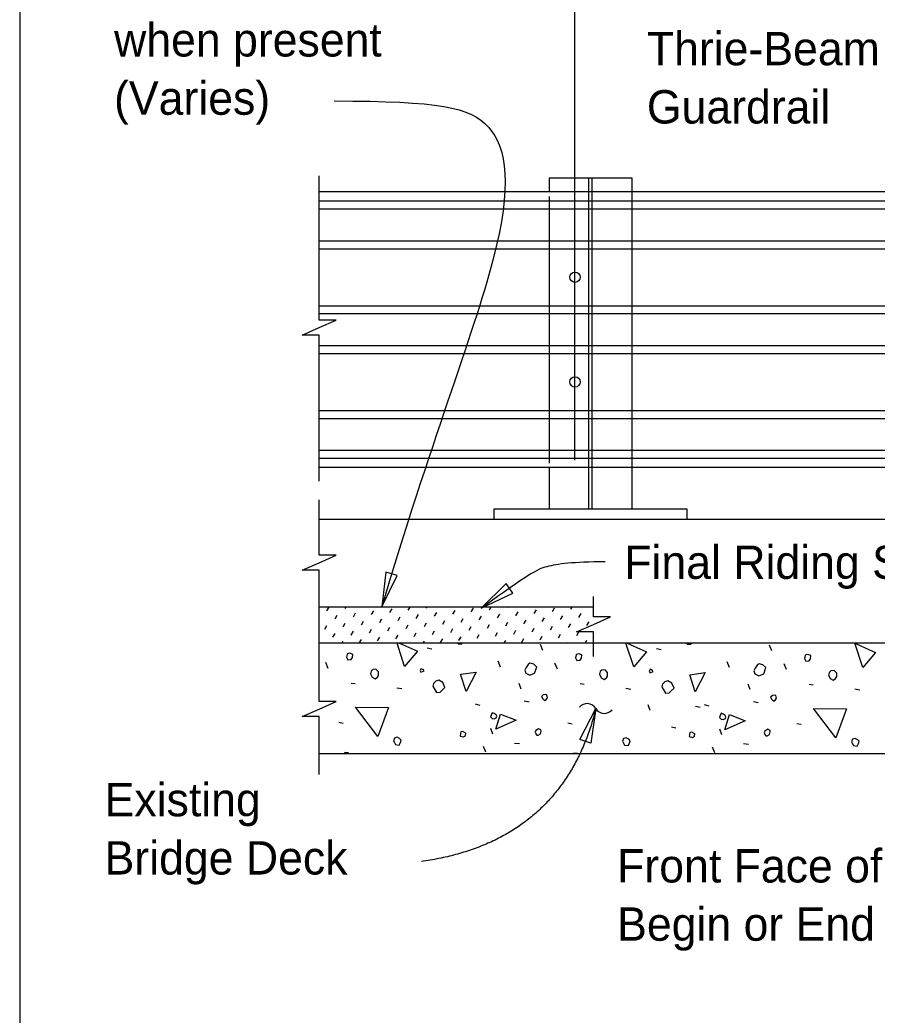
# Model space of a CAD drawing. Extents: x 21587 to 21656.3, y 56117.4 to 56157.3.
# Drawn here: x 21605.5 to 21610.68, y 56131.8 to 56137.82 of the extents above; entities that cross this region are included whole.
import ezdxf

# ---------------------------------------------------------------- set-up
doc = ezdxf.new("R2010")
doc.units = 0
for name, color, linetype in [('AdhocPoint_dp', 7, 'Continuous'), ('Border', 7, 'Continuous'), ('Patterning', 7, 'Continuous'), ('PlotBorder_dp', 7, 'Continuous'), ('SheetBorder_dp', 7, 'Continuous'), ('TextMisc', 7, 'Continuous')]:
    doc.layers.add(name, color=color, linetype=linetype)

msp = doc.modelspace()

# ---------------------------------------------------------------- linework, layer by layer
at = {"layer": 'AdhocPoint_dp'}
for p, q in [((21607.3117, 56134.8009), (21613.4854, 56134.8009)), ((21608.9696, 56134.2699), (21607.3116, 56134.2699)), ((21613.4854, 56134.0509), (21607.3117, 56134.0509)), ((21607.3117, 56133.3843), (21613.4854, 56133.3843))]:
    msp.add_line(p, q, dxfattribs=at)
at = {"layer": 'Border'}
for p, q in [((21608.7018, 56136.8635), (21609.2018, 56136.8635)), ((21608.7018, 56136.8635), (21608.7018, 56136.7802)), ((21609.2018, 56136.8635), (21609.2018, 56136.7802)), ((21619.5663, 56136.7801), (21607.3117, 56136.7801)), ((21607.3117, 56136.7246), (21619.5663, 56136.7246)), ((21607.3117, 56136.6764), (21619.5663, 56136.6764)), ((21607.3117, 56136.4835), (21619.5663, 56136.4835)), ((21607.3117, 56136.4353), (21619.5663, 56136.4353)), ((21607.3117, 56136.0914), (21619.5663, 56136.0914)), ((21607.3117, 56136.0431), (21619.5663, 56136.0431)), ((21607.3117, 56135.8503), (21619.5663, 56135.8503)), ((21607.3117, 56135.8022), (21619.5663, 56135.8022)), ((21607.3117, 56135.4582), (21619.5663, 56135.4582)), ((21607.3117, 56135.41), (21619.5663, 56135.41)), ((21607.3117, 56135.2172), (21619.5663, 56135.2172)), ((21607.3117, 56135.169), (21619.5663, 56135.169)), ((21619.5663, 56135.1134), (21607.3117, 56135.1134)), ((21608.7018, 56135.1135), (21608.7018, 56134.8635)), ((21609.2018, 56135.1134), (21609.2018, 56134.8635)), ((21608.3685, 56134.8635), (21609.5351, 56134.8635)), ((21608.3685, 56134.801), (21608.3685, 56134.8635)), ((21608.7018, 56134.8635), (21609.2018, 56134.8635)), ((21609.5351, 56134.8635), (21609.5351, 56134.801)), ((21608.3685, 56134.801), (21609.5351, 56134.801))]:
    msp.add_line(p, q, dxfattribs=at)
for centre in [(21608.858, 56136.2634), (21608.858, 56135.6303)]:
    msp.add_circle(centre, 0.0312, dxfattribs=at)
at = {"layer": 'Patterning'}
for p, q in [((21608.9414, 56134.8635), (21608.9414, 56136.8635)), ((21608.9622, 56134.8635), (21608.9622, 56136.8635)), ((21608.7018, 56136.7516), (21608.7018, 56135.1398)), ((21609.2018, 56136.7801), (21609.2018, 56135.1134))]:
    msp.add_line(p, q, dxfattribs=at)
at = {"layer": 'PlotBorder_dp'}
for p, q in [((21605.5022, 56153.2556), (21605.5022, 56127.3172)), ((21608.858, 56135.1577), (21608.858, 56143.2258))]:
    msp.add_line(p, q, dxfattribs=at)
for points in [[(21607.3117, 56135.0303), (21607.3117, 56135.9135), (21607.2084, 56135.9135), (21607.3117, 56135.9585), (21607.4151, 56136.0035), (21607.3117, 56136.0035), (21607.3117, 56136.8765)], [(21607.3117, 56134.0229), (21607.3117, 56134.493), (21607.2084, 56134.493), (21607.3117, 56134.538), (21607.4151, 56134.583), (21607.3117, 56134.583), (21607.3117, 56134.9175)], [(21608.9697, 56133.972), (21608.9697, 56134.1198), (21608.8664, 56134.1198), (21608.9697, 56134.1648), (21609.073, 56134.2098), (21608.9697, 56134.2098), (21608.9697, 56134.3343)], [(21607.3117, 56133.2578), (21607.3117, 56133.6084), (21607.2084, 56133.6084), (21607.3117, 56133.6534), (21607.4151, 56133.6984), (21607.3117, 56133.6984), (21607.3117, 56134.0229)]]:
    msp.add_lwpolyline(points, dxfattribs=at)
for points in [[(21607.6902, 56134.2707), (21607.7828, 56134.4606), (21607.7151, 56134.4805)], [(21608.2911, 56134.2633), (21608.4817, 56134.3543), (21608.4411, 56134.412)], [(21608.9843, 56133.6565), (21608.9539, 56133.4475), (21608.8867, 56133.4692)]]:
    msp.add_lwpolyline(points, close=True, dxfattribs=at)
for centre, start, end in [((21608.9319, 56133.6269), 30.00813, 141.73535), ((21609.0352, 56133.6865), 210.00813, 321.73535)]:
    msp.add_arc(centre, 0.0596, start, end, dxfattribs=at)
for points, degree in [([(21607.4013, 56137.3293), (21608.0354, 56137.3258), (21608.4135, 56137.2664), (21608.5135, 56136.5948), (21607.9729, 56135.2323), (21607.6902, 56134.2708)], 3), ([(21609.0397, 56134.5436), (21608.8463, 56134.5415), (21608.6579, 56134.5211), (21608.5865, 56134.4713), (21608.2911, 56134.2634)], 3), ([(21608.9843, 56133.6565), (21608.7812, 56132.8522), (21607.9297, 56132.7319)], 2)]:
    msp.add_open_spline(points, degree=degree, dxfattribs=at)
at = {"layer": 'TextMisc'}
for p, q in [((21607.3586, 56134.2474), (21607.3715, 56134.2698)), ((21607.4692, 56134.2604), (21607.4747, 56134.2699)), ((21607.8499, 56134.2504), (21607.8612, 56134.2699)), ((21607.9606, 56134.2634), (21607.9643, 56134.2699)), ((21608.3413, 56134.2535), (21608.3508, 56134.2699)), ((21608.4519, 56134.2664), (21608.4539, 56134.2699)), ((21608.722, 56134.2435), (21608.735, 56134.2659)), ((21608.8327, 56134.2565), (21608.8404, 56134.2699)), ((21608.9433, 56134.2695), (21608.9436, 56134.2699)), ((21607.4074, 56134.1986), (21607.4204, 56134.221)), ((21607.518, 56134.2116), (21607.531, 56134.234)), ((21607.6287, 56134.2245), (21607.6416, 56134.2469)), ((21607.7393, 56134.2375), (21607.7523, 56134.2599)), ((21607.7881, 56134.1887), (21607.8011, 56134.211)), ((21607.8988, 56134.2016), (21607.9117, 56134.224)), ((21608.0094, 56134.2146), (21608.0224, 56134.237)), ((21608.12, 56134.2275), (21608.133, 56134.2499)), ((21608.2307, 56134.2405), (21608.2436, 56134.2629)), ((21608.2795, 56134.1917), (21608.2925, 56134.2141)), ((21608.3901, 56134.2046), (21608.4031, 56134.227)), ((21608.5008, 56134.2176), (21608.5137, 56134.24)), ((21608.6114, 56134.2306), (21608.6244, 56134.253)), ((21608.7709, 56134.1947), (21608.7838, 56134.2171)), ((21608.8815, 56134.2077), (21608.8945, 56134.23)), ((21607.3456, 56134.1368), (21607.3586, 56134.1592)), ((21607.4562, 56134.1498), (21607.4692, 56134.1722)), ((21607.5669, 56134.1627), (21607.5798, 56134.1851)), ((21607.6775, 56134.1757), (21607.6905, 56134.1981)), ((21607.7263, 56134.1269), (21607.7393, 56134.1492)), ((21607.837, 56134.1398), (21607.8499, 56134.1622)), ((21607.9476, 56134.1528), (21607.9606, 56134.1752)), ((21608.0582, 56134.1657), (21608.0712, 56134.1881)), ((21608.1689, 56134.1787), (21608.1818, 56134.2011)), ((21608.2177, 56134.1299), (21608.2307, 56134.1523)), ((21608.3283, 56134.1428), (21608.3413, 56134.1652)), ((21608.439, 56134.1558), (21608.4519, 56134.1782)), ((21608.5496, 56134.1688), (21608.5626, 56134.1912)), ((21608.6602, 56134.1817), (21608.6732, 56134.2041)), ((21608.7091, 56134.1329), (21608.722, 56134.1553)), ((21608.8197, 56134.1459), (21608.8327, 56134.1682)), ((21608.9303, 56134.1588), (21608.9433, 56134.1812)), ((21607.3944, 56134.088), (21607.4074, 56134.1104)), ((21607.5051, 56134.1009), (21607.518, 56134.1233)), ((21607.6157, 56134.1139), (21607.6287, 56134.1363)), ((21607.6645, 56134.0651), (21607.6775, 56134.0874)), ((21607.7752, 56134.078), (21607.7881, 56134.1004)), ((21607.8858, 56134.091), (21607.8988, 56134.1134)), ((21607.9964, 56134.1039), (21608.0094, 56134.1263)), ((21608.1071, 56134.1169), (21608.12, 56134.1393)), ((21608.1559, 56134.0681), (21608.1689, 56134.0905)), ((21608.2665, 56134.081), (21608.2795, 56134.1034)), ((21608.3772, 56134.094), (21608.3901, 56134.1164)), ((21608.4878, 56134.107), (21608.5008, 56134.1294)), ((21608.5984, 56134.1199), (21608.6114, 56134.1423)), ((21608.6473, 56134.0711), (21608.6602, 56134.0935)), ((21608.7579, 56134.0841), (21608.7709, 56134.1065)), ((21608.8685, 56134.097), (21608.8815, 56134.1194)), ((21608.9792, 56134.11), (21608.9793, 56134.1102)), ((21607.4501, 56134.0509), (21607.4562, 56134.0615)), ((21607.5539, 56134.0521), (21607.5669, 56134.0745)), ((21607.8366, 56134.0509), (21607.837, 56134.0516)), ((21607.9397, 56134.0509), (21607.9476, 56134.0645)), ((21608.0453, 56134.0551), (21608.0582, 56134.0775)), ((21608.3262, 56134.0509), (21608.3283, 56134.0546)), ((21608.4293, 56134.0509), (21608.439, 56134.0676)), ((21608.5366, 56134.0581), (21608.5496, 56134.0805)), ((21608.6635, 56134.0079), (21608.6494, 56134.0432)), ((21608.8158, 56134.0509), (21608.8197, 56134.0576)), ((21608.919, 56134.0509), (21608.9303, 56134.0706)), ((21610.0482, 56134.0043), (21610.034, 56134.0397)), ((21607.9652, 56134.0238), (21607.9935, 56134.0167)), ((21609.3499, 56134.0203), (21609.3782, 56134.0132)), ((21607.3666, 56133.8989), (21607.3524, 56133.9343)), ((21608.4072, 56133.9071), (21608.393, 56133.9425)), ((21608.7513, 56133.8954), (21608.7371, 56133.9307)), ((21609.7919, 56133.9036), (21609.7777, 56133.9389)), ((21610.1359, 56133.8918), (21610.1218, 56133.9272)), ((21607.5045, 56133.8105), (21607.5292, 56133.807)), ((21608.5327, 56133.7745), (21608.5203, 56133.8081)), ((21608.8892, 56133.807), (21608.9139, 56133.8034)), ((21609.9174, 56133.771), (21609.905, 56133.8046)), ((21610.2738, 56133.8034), (21610.2986, 56133.7999)), ((21607.7802, 56133.7822), (21607.8103, 56133.7769)), ((21609.1649, 56133.7787), (21609.195, 56133.7734)), ((21610.5496, 56133.7752), (21610.5797, 56133.7699)), ((21608.2552, 56133.6844), (21608.2834, 56133.6773)), ((21608.5515, 56133.7027), (21608.5816, 56133.6974)), ((21609.3134, 56133.6443), (21609.301, 56133.6779)), ((21609.5874, 56133.6709), (21609.6157, 56133.6638)), ((21609.6398, 56133.6808), (21609.6681, 56133.6738)), ((21609.9362, 56133.6991), (21609.9662, 56133.6938)), ((21607.4302, 56133.5736), (21607.4567, 56133.5683)), ((21608.8149, 56133.5701), (21608.8414, 56133.5648)), ((21609.4407, 56133.5453), (21609.4672, 56133.54)), ((21610.1996, 56133.5666), (21610.2261, 56133.5613)), ((21608.3612, 56133.5018), (21608.3488, 56133.5354)), ((21609.7459, 56133.4982), (21609.7335, 56133.5318)), ((21608.3188, 56133.3922), (21608.3046, 56133.4275)), ((21608.4914, 56133.4481), (21608.5232, 56133.4446)), ((21609.7035, 56133.3886), (21609.6893, 56133.424)), ((21609.8761, 56133.4446), (21609.9079, 56133.4411))]:
    msp.add_line(p, q, dxfattribs=at)
for points in [[(21607.828, 56133.9113), (21607.7825, 56134.0509)], [(21607.7964, 56134.0509), (21607.9058, 56134.0032), (21607.828, 56133.9113)], [(21608.1516, 56134.0509), (21608.1526, 56134.0485), (21608.1502, 56134.0509)], [(21608.1526, 56134.0485), (21608.1738, 56134.0485), (21608.1762, 56134.0509)], [(21609.2127, 56133.9077), (21609.1661, 56134.0509)], [(21609.173, 56134.0509), (21609.2904, 56133.9997), (21609.2127, 56133.9077)], [(21609.5348, 56134.0509), (21609.5373, 56134.045), (21609.5338, 56134.0485)], [(21609.5373, 56134.045), (21609.5585, 56134.045), (21609.5644, 56134.0509)], [(21610.5973, 56133.9042), (21610.5496, 56134.0509), (21610.6751, 56133.9961), (21610.5973, 56133.9042)], [(21607.4762, 56133.9661), (21607.485, 56133.9502), (21607.5045, 56133.9519), (21607.5133, 56133.9643), (21607.5151, 56133.9838), (21607.5027, 56133.9891), (21607.4939, 56133.9908), (21607.4833, 56133.9873), (21607.4797, 56133.9838), (21607.4762, 56133.9661)], [(21608.8609, 56133.9625), (21608.8697, 56133.9466), (21608.8892, 56133.9484), (21608.898, 56133.9608), (21608.8998, 56133.9802), (21608.8874, 56133.9855), (21608.8785, 56133.9873), (21608.8679, 56133.9838), (21608.8644, 56133.9802), (21608.8609, 56133.9625)], [(21610.2455, 56133.959), (21610.2544, 56133.9431), (21610.2738, 56133.9449), (21610.2827, 56133.9572), (21610.2844, 56133.9767), (21610.2721, 56133.982), (21610.2632, 56133.9838), (21610.2526, 56133.9802), (21610.2491, 56133.9767), (21610.2455, 56133.959)], [(21608.561, 56133.87), (21608.584, 56133.8576), (21608.614, 56133.87), (21608.6264, 56133.9071), (21608.6087, 56133.9248), (21608.5857, 56133.9301), (21608.5751, 56133.923), (21608.5627, 56133.9036), (21608.5539, 56133.8877), (21608.561, 56133.87)], [(21609.9457, 56133.8665), (21609.9686, 56133.8541), (21609.9987, 56133.8665), (21610.0111, 56133.9036), (21609.9934, 56133.9213), (21609.9704, 56133.9266), (21609.9598, 56133.9195), (21609.9474, 56133.9), (21609.9386, 56133.8841), (21609.9457, 56133.8665)], [(21607.6211, 56133.8671), (21607.6318, 56133.8459), (21607.6494, 56133.8353), (21607.6636, 56133.8459), (21607.6706, 56133.8565), (21607.6706, 56133.8777), (21607.6547, 56133.8936), (21607.6353, 56133.8918), (21607.6265, 56133.883), (21607.6211, 56133.8671)], [(21607.927, 56133.8759), (21607.9464, 56133.8848), (21607.9393, 56133.8918), (21607.927, 56133.8971), (21607.9217, 56133.8848), (21607.927, 56133.8759)], [(21608.2003, 56133.7604), (21608.1668, 56133.8647), (21608.2605, 56133.8771), (21608.2003, 56133.7604)], [(21609.0058, 56133.8635), (21609.0164, 56133.8423), (21609.0341, 56133.8317), (21609.0483, 56133.8423), (21609.0553, 56133.8529), (21609.0553, 56133.8742), (21609.0394, 56133.8901), (21609.02, 56133.8883), (21609.0111, 56133.8795), (21609.0058, 56133.8635)], [(21609.3116, 56133.8724), (21609.3311, 56133.8812), (21609.324, 56133.8883), (21609.3116, 56133.8936), (21609.3063, 56133.8812), (21609.3116, 56133.8724)], [(21609.585, 56133.7569), (21609.5514, 56133.8612), (21609.6451, 56133.8735), (21609.585, 56133.7569)], [(21610.3905, 56133.86), (21610.4011, 56133.8388), (21610.4188, 56133.8282), (21610.4329, 56133.8388), (21610.44, 56133.8494), (21610.44, 56133.8706), (21610.4241, 56133.8865), (21610.4046, 56133.8848), (21610.3958, 56133.8759), (21610.3905, 56133.86)], [(21607.9977, 56133.7911), (21608.0207, 56133.7539), (21608.0436, 56133.7557), (21608.0525, 56133.7646), (21608.0719, 56133.784), (21608.0596, 56133.814), (21608.0348, 56133.8282), (21608.0171, 56133.8211), (21608.003, 56133.807), (21607.9977, 56133.7911)], [(21609.3824, 56133.7875), (21609.4053, 56133.7504), (21609.4283, 56133.7522), (21609.4372, 56133.761), (21609.4566, 56133.7805), (21609.4442, 56133.8105), (21609.4195, 56133.8247), (21609.4018, 56133.8176), (21609.3877, 56133.8034), (21609.3824, 56133.7875)], [(21608.6629, 56133.7151), (21608.6735, 56133.7044), (21608.6841, 56133.7115), (21608.6912, 56133.7221), (21608.6876, 56133.7398), (21608.6788, 56133.7416), (21608.6664, 56133.7398), (21608.6558, 56133.7292), (21608.6629, 56133.7151)], [(21610.0476, 56133.7115), (21610.0582, 56133.7009), (21610.0688, 56133.708), (21610.0758, 56133.7186), (21610.0723, 56133.7363), (21610.0635, 56133.738), (21610.0511, 56133.7363), (21610.0405, 56133.7257), (21610.0476, 56133.7115)], [(21607.6653, 56133.487), (21607.531, 56133.6638), (21607.7307, 56133.662), (21607.6653, 56133.487)], [(21608.3577, 56133.596), (21608.3701, 56133.5942), (21608.3824, 56133.5995), (21608.386, 56133.6101), (21608.3807, 56133.619), (21608.3701, 56133.626), (21608.3577, 56133.6313), (21608.3506, 56133.6172), (21608.3471, 56133.6066), (21608.3577, 56133.596)], [(21608.38, 56133.5312), (21608.4083, 56133.6231), (21608.502, 56133.586), (21608.38, 56133.5312)], [(21609.7424, 56133.5925), (21609.7547, 56133.5907), (21609.7671, 56133.596), (21609.7706, 56133.6066), (21609.7653, 56133.6154), (21609.7547, 56133.6225), (21609.7424, 56133.6278), (21609.7353, 56133.6137), (21609.7318, 56133.6031), (21609.7424, 56133.5925)], [(21609.7647, 56133.5277), (21609.793, 56133.6196), (21609.8867, 56133.5825), (21609.7647, 56133.5277)], [(21610.4347, 56133.4799), (21610.3003, 56133.6567), (21610.5001, 56133.655), (21610.4347, 56133.4799)], [(21607.7643, 56133.4552), (21607.7732, 56133.4393), (21607.7944, 56133.4357), (21607.8032, 56133.4517), (21607.8068, 56133.4658), (21607.7979, 56133.4746), (21607.782, 56133.4835), (21607.7661, 56133.4782), (21607.7608, 56133.4623), (21607.7643, 56133.4552)], [(21608.1639, 56133.4905), (21608.1833, 56133.4852), (21608.1957, 56133.4941), (21608.1974, 56133.5065), (21608.1939, 56133.51), (21608.1798, 56133.5171), (21608.1674, 56133.5153), (21608.1656, 56133.5029), (21608.1639, 56133.4905)], [(21608.6275, 56133.4959), (21608.6346, 56133.4959), (21608.6487, 56133.5029), (21608.654, 56133.5188), (21608.6523, 56133.5277), (21608.6381, 56133.5347), (21608.6205, 56133.5241), (21608.6169, 56133.5135), (21608.6205, 56133.5029), (21608.6275, 56133.4959)], [(21609.5485, 56133.487), (21609.568, 56133.4817), (21609.5803, 56133.4905), (21609.5821, 56133.5029), (21609.5786, 56133.5065), (21609.5644, 56133.5135), (21609.5521, 56133.5118), (21609.5503, 56133.4994), (21609.5485, 56133.487)], [(21610.0122, 56133.4923), (21610.0193, 56133.4923), (21610.0334, 56133.4994), (21610.0387, 56133.5153), (21610.0369, 56133.5241), (21610.0228, 56133.5312), (21610.0051, 56133.5206), (21610.0016, 56133.51), (21610.0051, 56133.4994), (21610.0122, 56133.4923)], [(21609.149, 56133.4517), (21609.1579, 56133.4357), (21609.1791, 56133.4322), (21609.1879, 56133.4481), (21609.1914, 56133.4623), (21609.1826, 56133.4711), (21609.1667, 56133.4799), (21609.1508, 56133.4746), (21609.1455, 56133.4587), (21609.149, 56133.4517)], [(21610.5337, 56133.4481), (21610.5425, 56133.4322), (21610.5637, 56133.4287), (21610.5726, 56133.4446), (21610.5761, 56133.4587), (21610.5673, 56133.4676), (21610.5514, 56133.4764), (21610.5355, 56133.4711), (21610.5302, 56133.4552), (21610.5337, 56133.4481)], [(21607.4896, 56133.3843), (21607.4886, 56133.388), (21607.4656, 56133.3898), (21607.4637, 56133.3843)], [(21608.8733, 56133.3843), (21608.8732, 56133.3845), (21608.8503, 56133.3862), (21608.8496, 56133.3843)]]:
    msp.add_lwpolyline(points, dxfattribs=at)

# ---------------------------------------------------------------- texts
at = {"layer": 'PlotBorder_dp'}
for s, p in [('when present', (21606.0715, 56137.5973)), ('Thrie-Beam ', (21609.2926, 56137.5444)), ('(Varies)', (21606.0715, 56137.2453)), ('Guardrail', (21609.2926, 56137.1924)), ('Existing ', (21606.0143, 56133.0052)), ('Bridge Deck', (21606.0143, 56132.6532)), ('Front Face of Backwall &', (21609.1128, 56132.6051)), ('Begin or End Bridge', (21609.1128, 56132.2531))]:
    msp.add_text(s, height=0.2016, dxfattribs=at).set_placement(p)
at = {"layer": 'SheetBorder_dp'}
msp.add_text('Final Riding Surface', height=0.2016, dxfattribs=at).set_placement((21609.1559, 56134.44))

doc.saveas('drawing.dxf')
